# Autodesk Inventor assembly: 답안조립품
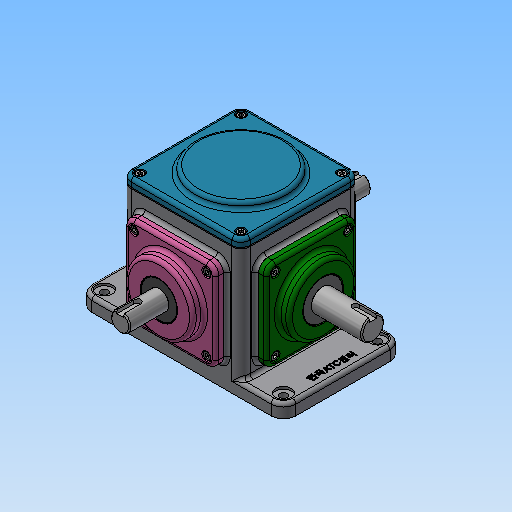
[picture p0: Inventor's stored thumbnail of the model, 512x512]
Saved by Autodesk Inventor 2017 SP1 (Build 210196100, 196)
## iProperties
Part Number: 답안조립품
Material: 일반
Document SubType Name: Assembly
Designer: MRC
Mass: 3235.88 g
Surface Area: 2651.69 cm^2
Volume: 866.536 cm^3
Density: 3.73427 g/cm^3
Author: MRC
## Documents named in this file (20)
- C:\Users\MRC\Desktop\620307V1005\답안조립품.iam
- C:\Users\MRC\Desktop\620307V1005\본체.ipt
- C:\Users\MRC\Desktop\620307V1005\개스킷.ipt
- C:\Users\MRC\Desktop\620307V1005\메인베벨기어.ipt
- C:\Users\MRC\Desktop\620307V1005\메인축.ipt
- C:\Users\MRC\Desktop\620307V1005\메인커버.ipt
- C:\Users\MRC\Desktop\620307V1005\베어링 6203.ipt
- C:\Users\MRC\Desktop\620307V1005\베어링 6204.ipt
- C:\Users\MRC\Desktop\620307V1005\볼트 M4.ipt
- C:\Users\MRC\Desktop\620307V1005\상부커버.ipt
- C:\Users\MRC\Desktop\620307V1005\서브베벨기어.ipt
- C:\Users\MRC\Desktop\620307V1005\서브축.ipt
- C:\Users\MRC\Desktop\620307V1005\서브커버.ipt
- C:\Users\MRC\Desktop\620307V1005\오일 실 17 32 8.ipt
- C:\Users\MRC\Desktop\620307V1005\오일 실 20 35 8.ipt
- C:\Users\MRC\Desktop\620307V1005\키 4x4.ipt
- C:\Users\MRC\Desktop\620307V1005\서브베벨기어_MIR.ipt
- C:\Users\MRC\Desktop\620307V1005\서브축_MIR.ipt
- C:\Users\MRC\Desktop\620307V1005\서브커버_MIR.ipt
- C:\Users\MRC\Desktop\620307V1005\키 4x4_MIR.ipt
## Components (1 placed, 1 different names)
1. 개스킷:1
